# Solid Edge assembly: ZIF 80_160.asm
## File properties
Title: Zylinder
Author: bmolnar
Template: iso metric assembly.asm
Last saved by: psaghy
Revision: 32
Application: Solid Edge
Username: bmolnar
Dokumentum tartalom típus: 1
Document Number: ZIF 80/160
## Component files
Kolbenstange.par
Kit_1.par
Kit_2.par
Profilrohr.par
Mutter.par
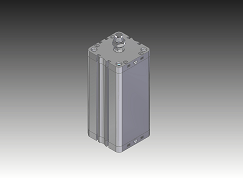
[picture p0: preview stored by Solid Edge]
